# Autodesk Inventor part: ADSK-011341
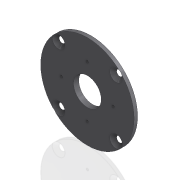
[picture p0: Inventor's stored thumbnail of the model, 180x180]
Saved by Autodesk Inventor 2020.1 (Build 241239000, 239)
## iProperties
Created: 1999-12
Part Number: ADSK-011341
Material: Acier doux
Description: PLT-09,FC,CP,03,067,058,034,ADAPTER,INDRAMAT_MOTOR,MKD041
Document SubType Name: Modeling
Designer: tgregory
Density: 7.86 g/cm^3
Appearance: Metal-Steel(Polish)
Mass: 1204.39 g
Surface Area: 483.831 cm^2
Volume: 153.23 cm^3
Control State: 0
Checked Out: False
Master: False
Shininess: 0.0
Length Units: 11269
Angle Units: 11279
Time Units: 11290
Mass Units: 11283
Length Display Precision: 3
Angle Display Precision: 2
Compacted: True
Dimensions: 171,4x171,4x9,5 mm
Mass: 1,204 kg
Density: 0.0
Volumn: 0.0
Area: 0.0
PropertySet Name: Model Information
Author: tgregory
Revision Number: -
Title: PLT-09,FC,CP,03,067,058,034,ADAPTER,INDRAMAT_MOTOR,MKD041
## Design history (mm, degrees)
node "Extrusion1" dims "d1" = 9.525, "d2" = 0
node "Extrusion2" dims "d4" = 9.525, "d5" = 0
node "Hole1" dims "d7" = 4.134, "d8" = 9.525, "d9" = 6.35, "d10" = 60 deg, "d11" = 14.2, "d12" = 118 deg, "d25" = 10
  sketch "Sketch3"
    geometry: L1 (0, 0)-(0, 47.5); L2 (0, 0)-(47.5, 0); L3 (0, 0)-(0, -47.5); L4 (0, 0)-(-47.5, 0); C1 r 85.725 at (0, 0) reference; A1 r 47.5 centre (0, 0) between (0, 47.5) and (47.5, 0); 4 further points
    constraints: 8 end point, 5 coincident, 4 point on circle, 3 perpendicular, 1 centre point, 1 vertical
    dimensions: "d6" = 95 diameter of A1
node "Hole2" dims "d15" = 11, "d16" = 23.5, "d17" = 6.35, "d18" = 90 deg, "d19" = 19.05, "d20" = 118 deg, "d24" = 6
node "Extrusion3" dims "d22" = 3.175, "d23" = 0
node "Solide1"
node "Corps solides"
node "Corps surfaciques"
sketch "Sketch1"
  geometry: C1 r 85.725 at (0, 0); 1 further point
  constraints: 1 centre point, 1 coincident
  dimensions: "d0" = 171.45 diameter of C1
sketch "Sketch2"
  geometry: C1 r 85.725 at (0, 0) reference; C2 r 25.4 at (0, 0)
  constraints: 1 centre point, 1 coincident
  dimensions: "d3" = 50.8 diameter of C2
sketch "Sketch4"
  geometry: L1 (0, 0)-(-60.617, 60.617); L2 (0, 0)-(60.617, 60.617); L3 (0, 0)-(60.617, -60.617); L4 (0, 0)-(-60.617, -60.617); L5 (0, 0)-(85.725, 0); A1 r 85.725 centre (0, 0) between (-60.617, 60.617) and (60.617, 60.617) reference; A2 r 74.612 centre (0, 0) between (-52.759, 52.759) and (-52.759, -52.759); 2 further points
  constraints: 10 end point, 9 point on circle, 4 point on line, 3 perpendicular, 1 centre point, 1 coincident, 1 horizontal
  dimensions: "d13" = 149.225 diameter of A2; "d14" = 45 deg angle of L2 L5
sketch "Sketch5"
  geometry: C1 r 85.725 at (0, 0) reference; C2 r 57.15 at (0, 0)
  constraints: 1 centre point, 1 coincident
  dimensions: "d21" = 114.3 diameter of C2
